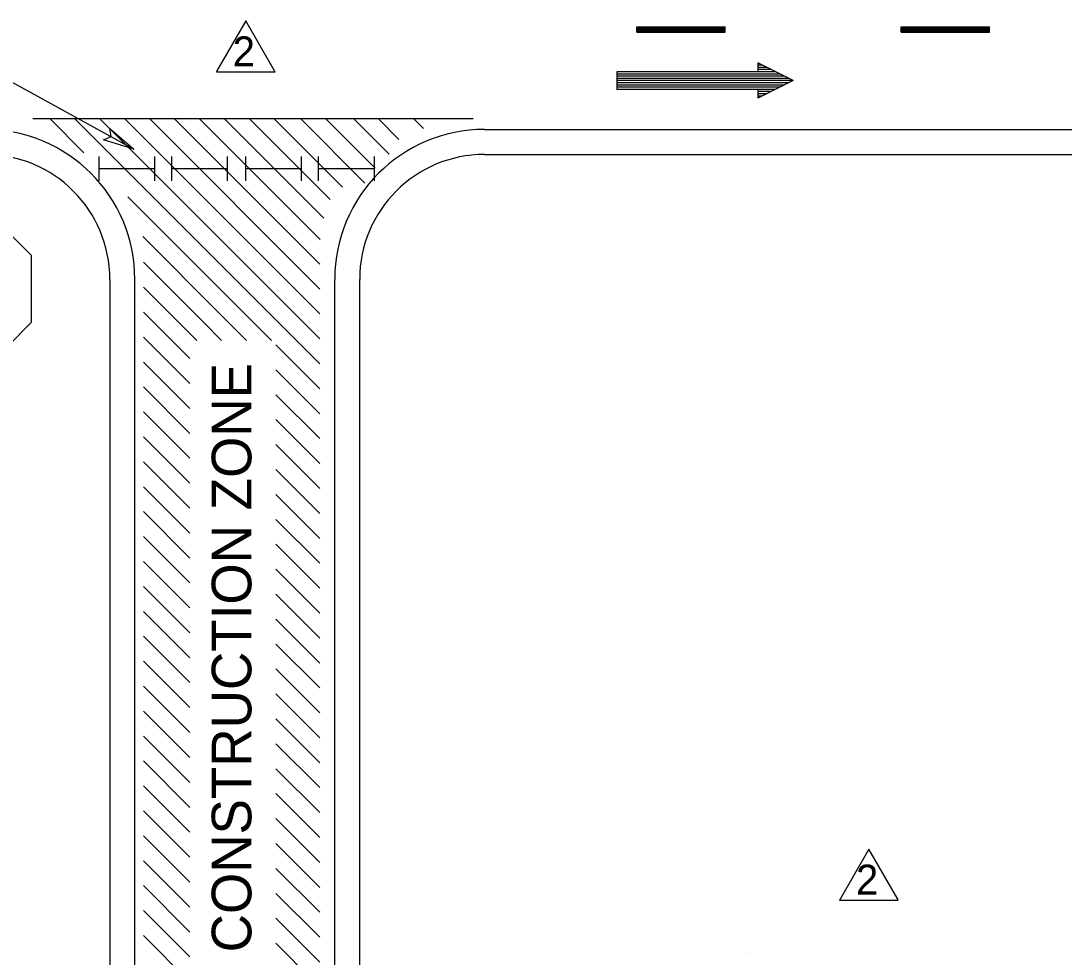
# Model space of a CAD drawing. Extents: x 1482 to 1692, y 225 to 494.
# Drawn here: x 1536.8 to 1587.3, y 337.4 to 382.7 of the extents above; entities that cross this region are included whole.
import ezdxf

# ---------------------------------------------------------------- set-up
doc = ezdxf.new("R2010")
doc.units = 0
for name, color, linetype in [('Level 10', 7, 'Continuous'), ('Level 17', 7, 'Continuous'), ('Level 2', 7, 'Continuous'), ('Level 60', 7, 'Continuous')]:
    doc.layers.add(name, color=color, linetype=linetype)

msp = doc.modelspace()

# ---------------------------------------------------------------- linework, layer by layer
at = {"layer": 'Level 10'}
for p, q in [((1540.557, 374.952), (1540.557, 376.131)), ((1543.257, 374.952), (1543.257, 376.131)), ((1544.08, 374.952), (1544.08, 376.131)), ((1546.78, 374.952), (1546.78, 376.131)), ((1547.668, 374.952), (1547.668, 376.131)), ((1550.368, 374.952), (1550.368, 376.131)), ((1551.191, 374.952), (1551.191, 376.131)), ((1553.891, 374.952), (1553.891, 376.131)), ((1540.557, 375.538), (1543.257, 375.538)), ((1544.08, 375.538), (1546.78, 375.538)), ((1547.668, 375.538), (1550.368, 375.538)), ((1551.191, 375.538), (1553.891, 375.538))]:
    msp.add_line(p, q, dxfattribs=at)
at = {"layer": 'Level 17'}
for p, q in [((1535.123, 380.389), (1542.24, 376.488)), ((1571.96, 337.545), (1571.96, 337.545)), ((1571.96, 337.545), (1571.96, 337.545)), ((1571.96, 337.545), (1571.96, 337.545)), ((1571.96, 337.545), (1571.96, 337.545)), ((1571.96, 337.545), (1571.96, 337.545)), ((1571.96, 337.545), (1571.96, 337.545)), ((1571.96, 337.545), (1571.96, 337.545)), ((1571.96, 337.545), (1571.96, 337.545)), ((1572.146, 337.553), (1572.146, 337.553)), ((1572.146, 337.553), (1572.146, 337.553)), ((1572.146, 337.553), (1572.146, 337.553)), ((1572.146, 337.553), (1572.146, 337.553))]:
    msp.add_line(p, q, dxfattribs=at)
msp.add_lwpolyline([(1531.716, 365.791), (1529.422, 368.084), (1529.422, 371.352), (1531.716, 373.645), (1534.983, 373.645), (1537.275, 371.352), (1537.275, 368.084), (1534.983, 365.791)], close=True, dxfattribs=at)
at = {"layer": 'Level 2'}
for p, q in [((1566.6, 382.403), (1570.866, 382.403)), ((1566.6, 382.147), (1566.6, 382.403)), ((1570.866, 382.147), (1570.866, 382.403)), ((1579.399, 382.403), (1583.666, 382.403)), ((1579.399, 382.147), (1579.399, 382.403)), ((1583.666, 382.147), (1583.666, 382.403)), ((1566.6, 382.339), (1570.866, 382.339)), ((1566.6, 382.275), (1570.866, 382.275)), ((1566.6, 382.211), (1570.866, 382.211)), ((1566.6, 382.147), (1570.866, 382.147)), ((1579.399, 382.339), (1583.666, 382.339)), ((1579.399, 382.275), (1583.666, 382.275)), ((1579.399, 382.211), (1583.666, 382.211)), ((1579.399, 382.147), (1583.666, 382.147)), ((1574.16, 379.798), (1572.453, 380.652)), ((1572.453, 380.652), (1572.453, 380.225)), ((1572.667, 380.545), (1572.453, 380.545)), ((1572.88, 380.438), (1572.453, 380.438)), ((1572.453, 380.225), (1565.627, 380.225)), ((1565.627, 380.225), (1565.627, 379.372)), ((1573.307, 380.225), (1565.627, 380.225)), ((1573.52, 380.118), (1565.627, 380.118)), ((1573.733, 380.012), (1565.627, 380.012)), ((1573.947, 379.905), (1565.627, 379.905)), ((1573.093, 380.332), (1572.453, 380.332)), ((1574.16, 379.798), (1565.627, 379.798)), ((1573.947, 379.692), (1565.627, 379.692)), ((1573.733, 379.585), (1565.627, 379.585)), ((1573.52, 379.478), (1565.627, 379.478)), ((1572.453, 379.372), (1565.627, 379.372)), ((1573.307, 379.372), (1565.627, 379.372)), ((1574.16, 379.798), (1572.453, 378.945)), ((1572.453, 379.372), (1572.453, 378.945)), ((1573.093, 379.265), (1572.453, 379.265)), ((1572.88, 379.158), (1572.453, 379.158)), ((1572.667, 379.052), (1572.453, 379.052)), ((1537.345, 377.957), (1558.677, 377.957)), ((1538.169, 377.957), (1539.827, 376.299)), ((1539.375, 377.957), (1551.241, 366.092)), ((1540.581, 377.957), (1551.241, 367.298)), ((1541.788, 377.957), (1551.241, 368.505)), ((1542.995, 377.957), (1551.241, 369.712)), ((1544.202, 377.957), (1551.241, 370.919)), ((1545.409, 377.957), (1551.264, 372.102)), ((1546.615, 377.957), (1551.438, 373.135)), ((1547.822, 377.957), (1551.741, 374.038)), ((1549.028, 377.957), (1552.344, 374.641)), ((1550.316, 377.957), (1553.434, 374.839)), ((1551.524, 377.957), (1553.928, 375.553)), ((1552.885, 377.957), (1554.609, 376.233)), ((1554.073, 377.957), (1555.077, 376.953)), ((1555.786, 377.957), (1556.26, 377.483)), ((1559.225, 377.436), (1620.696, 377.436)), ((1559.225, 376.227), (1620.696, 376.227)), ((1541.957, 374.169), (1547.669, 368.457)), ((1542.67, 372.248), (1546.462, 368.457)), ((1542.708, 371.004), (1545.629, 368.083)), ((1541.08, 370.179), (1541.08, 331.153)), ((1542.29, 331.153), (1542.29, 370.179)), ((1542.708, 369.798), (1545.285, 367.22)), ((1551.968, 331.153), (1551.968, 370.179)), ((1553.177, 331.153), (1553.177, 370.179)), ((1542.708, 368.591), (1544.952, 366.347)), ((1546.462, 368.457), (1547.699, 367.22)), ((1547.669, 368.457), (1548.906, 367.22)), ((1545.629, 368.083), (1546.492, 367.22)), ((1542.708, 367.385), (1544.952, 365.141)), ((1545.026, 367.48), (1545.286, 367.22)), ((1549.117, 367.009), (1551.241, 364.885)), ((1542.708, 366.177), (1544.952, 363.933)), ((1549.117, 365.802), (1551.241, 363.678)), ((1542.708, 364.971), (1544.952, 362.726)), ((1549.117, 364.595), (1551.241, 362.471)), ((1542.708, 363.764), (1544.952, 361.52)), ((1549.117, 363.389), (1551.241, 361.265)), ((1542.708, 362.557), (1544.952, 360.313)), ((1549.117, 362.182), (1551.241, 360.058)), ((1542.708, 361.35), (1544.952, 359.106)), ((1549.117, 360.975), (1551.241, 358.851)), ((1542.708, 360.143), (1544.952, 357.899)), ((1549.117, 359.768), (1551.241, 357.644)), ((1542.708, 358.937), (1544.952, 356.692)), ((1549.117, 358.561), (1551.241, 356.437)), ((1542.708, 357.73), (1544.952, 355.486)), ((1549.117, 357.355), (1551.241, 355.231)), ((1542.708, 356.524), (1544.952, 354.279)), ((1549.117, 356.148), (1551.241, 354.024)), ((1542.708, 355.316), (1544.952, 353.072)), ((1549.117, 354.941), (1551.241, 352.817)), ((1542.708, 354.11), (1544.952, 351.865)), ((1549.117, 353.734), (1551.241, 351.61)), ((1542.708, 352.903), (1544.952, 350.659)), ((1549.117, 352.528), (1551.241, 350.404)), ((1542.708, 351.696), (1544.952, 349.452)), ((1549.117, 351.321), (1551.241, 349.197)), ((1542.708, 350.49), (1544.952, 348.246)), ((1549.117, 350.115), (1551.241, 347.991)), ((1542.708, 349.282), (1544.952, 347.038)), ((1549.117, 348.907), (1551.241, 346.783)), ((1542.708, 348.076), (1544.952, 345.832)), ((1549.117, 347.7), (1551.241, 345.577)), ((1542.708, 346.869), (1544.952, 344.625)), ((1549.117, 346.494), (1551.241, 344.37)), ((1542.708, 345.663), (1544.952, 343.418)), ((1549.117, 345.287), (1551.241, 343.163)), ((1542.708, 344.456), (1544.952, 342.212)), ((1549.117, 344.081), (1551.241, 341.957)), ((1542.708, 343.249), (1544.952, 341.004)), ((1549.117, 342.873), (1551.241, 340.749)), ((1542.708, 342.042), (1544.952, 339.798)), ((1549.117, 341.667), (1551.241, 339.543)), ((1542.708, 340.836), (1544.952, 338.591)), ((1549.117, 340.46), (1551.241, 338.336)), ((1542.708, 339.629), (1544.952, 337.385)), ((1549.117, 339.254), (1551.241, 337.13)), ((1542.708, 338.422), (1552.014, 329.114)), ((1549.117, 338.047), (1551.39, 335.774))]:
    msp.add_line(p, q, dxfattribs=at)
msp.add_lwpolyline([(1542.24, 376.488), (1540.776, 376.937), (1541.142, 377.09), (1541.074, 377.481)], close=True, dxfattribs=at)
for centre, radius, start, end in [((1535.032, 370.179), 7.258, 0, 90), ((1559.225, 370.179), 7.258, 90, 180), ((1535.032, 370.179), 6.048, 0, 90), ((1559.225, 370.179), 6.048, 90, 180)]:
    msp.add_arc(centre, radius, start, end, dxfattribs=at)
at = {"layer": 'Level 60'}
for points in [[(1547.657, 382.69), (1546.264, 380.265)], [(1549.051, 380.265), (1547.657, 382.69)], [(1546.264, 380.265), (1546.238, 380.22), (1549.077, 380.22), (1549.051, 380.265)], [(1577.835, 342.605), (1576.442, 340.18)], [(1579.229, 340.18), (1577.835, 342.605)], [(1576.442, 340.18), (1576.416, 340.135), (1579.255, 340.135), (1579.229, 340.18)]]:
    msp.add_lwpolyline(points, dxfattribs=at)

# ---------------------------------------------------------------- texts
at = {"layer": 'Level 2'}
msp.add_text('CONSTRUCTION ZONE', height=1.91998, rotation=90, dxfattribs=at).set_placement((1547.933, 337.607))
at = {"layer": 'Level 60'}
for p in [(1547.03, 380.489), (1577.208, 340.404)]:
    msp.add_text('2', height=1.448, rotation=360, dxfattribs=at).set_placement(p)

doc.saveas('drawing.dxf')
